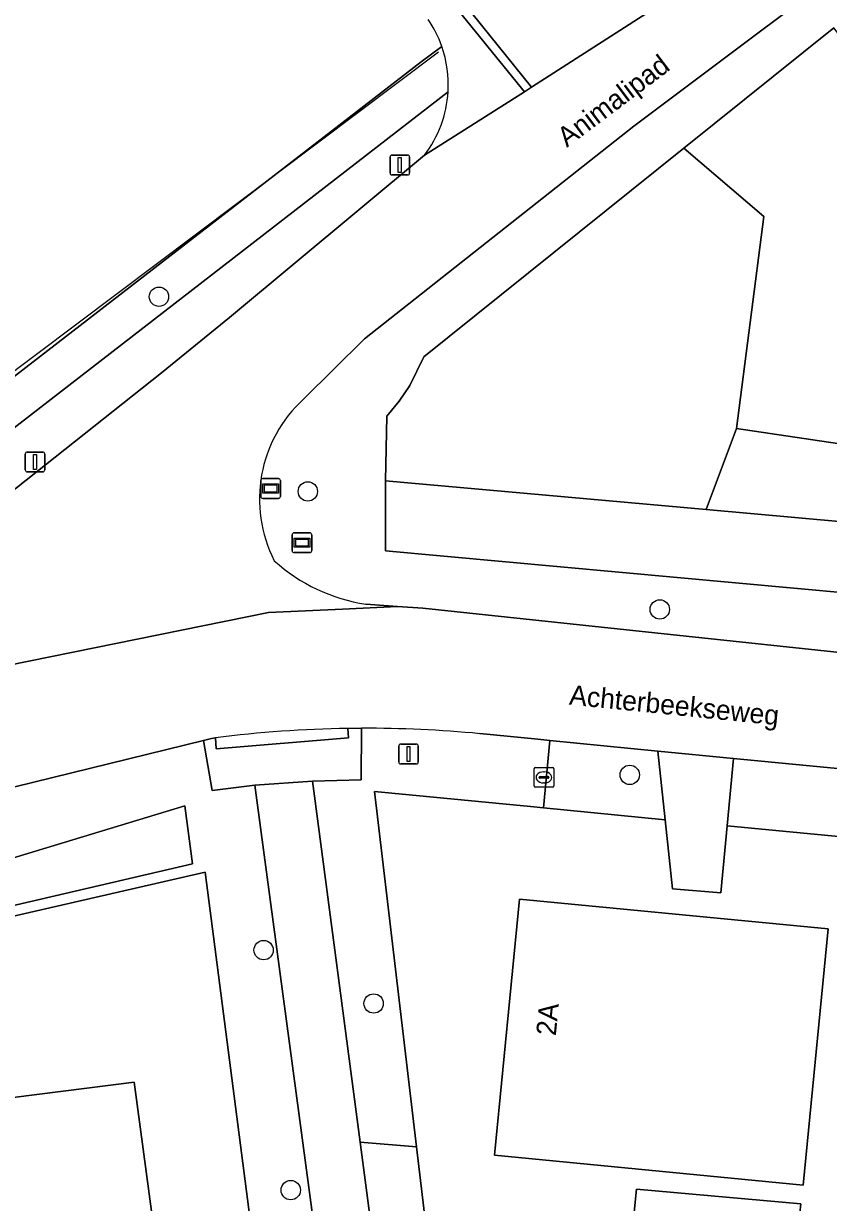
# Model space of a CAD drawing. Extents: x 162156 to 163172, y 378995 to 380779.
# Drawn here: x 162333 to 162373.7, y 380168.4 to 380227.9 of the extents above; entities that cross this region are included whole.
import ezdxf

# ---------------------------------------------------------------- set-up
doc = ezdxf.new("R2010")
doc.units = 0
for name, color, linetype in [('IMGEO_Boom', 7, 'Continuous'), ('IMGEO_Brandkraan', 7, 'Continuous'), ('IMGEO_Erf', 7, 'Continuous'), ('IMGEO_Grasland_overig', 7, 'Continuous'), ('IMGEO_Groenvoorziening', 7, 'Continuous'), ('IMGEO_Hek', 7, 'Continuous'), ('IMGEO_Lichtmast', 7, 'Continuous'), ('IMGEO_Loofbos', 7, 'Continuous'), ('IMGEO_Openbare_ruimte_label', 7, 'Continuous'), ('IMGEO_Pand', 7, 'Continuous'), ('IMGEO_Pand_nummerreeks', 7, 'Continuous'), ('IMGEO_Rijbaan_lokaal_gesloten', 7, 'Continuous'), ('IMGEO_Rijbaan_lokaal_open', 7, 'Continuous'), ('IMGEO_Straatnaambord', 7, 'Continuous'), ('IMGEO_Voetpad_open', 7, 'Continuous'), ('IMGEO_Waterloop', 7, 'Continuous')]:
    doc.layers.add(name, color=color, linetype=linetype)

msp = doc.modelspace()

# ---------------------------------------------------------------- linework, layer by layer
at = {"layer": 'IMGEO_Boom'}
for centre in [(162339.876, 380214.136), (162347.394, 380204.297), (162365.171, 380198.335), (162363.653, 380189.975), (162345.16, 380181.12), (162350.718, 380178.424), (162346.531, 380168.995)]:
    msp.add_circle(centre, 0.489, dxfattribs=at)
at = {"layer": 'IMGEO_Brandkraan'}
for p, q in [((162358.819, 380189.422), (162358.819, 380190.274)), ((162358.894, 380190.348), (162359.746, 380190.348)), ((162359.307, 380190.128), (162359.332, 380190.128)), ((162359.82, 380190.274), (162359.82, 380189.422)), ((162359.078, 380189.842), (162359.078, 380189.854)), ((162359.516, 380189.805), (162359.118, 380189.805)), ((162359.121, 380189.891), (162359.519, 380189.891)), ((162359.33, 380189.568), (162359.305, 380189.568)), ((162359.562, 380189.854), (162359.562, 380189.842)), ((162359.746, 380189.348), (162358.894, 380189.348))]:
    msp.add_line(p, q, dxfattribs=at)
for points in [[(162358.819, 380189.422), (162358.819, 380190.274)], [(162358.894, 380190.348), (162359.746, 380190.348)], [(162359.82, 380190.274), (162359.82, 380189.422)], [(162359.746, 380189.348), (162358.894, 380189.348)]]:
    msp.add_lwpolyline(points, dxfattribs=at)
for centre, radius, start, end in [((162358.896, 380190.272), 0.0765, 91.55205, 178.44795), ((162358.896, 380190.272), 0.0765, 91.55205, 178.44795), ((162359.744, 380190.272), 0.0765, 1.55205, 88.44795), ((162359.744, 380190.272), 0.0765, 1.55205, 88.44795), ((162358.896, 380189.424), 0.0765, 181.55205, 268.44795), ((162358.896, 380189.424), 0.0765, 181.55205, 268.44795), ((162359.118, 380189.851), 0.0403, 85.87752, 175.75265), ((162359.115, 380189.841), 0.0366, 178.93798, 274.71019), ((162359.519, 380189.848), 0.043, 264.86636, 352.45326), ((162359.523, 380189.853), 0.0386, 1.73085, 96.63898), ((162359.744, 380189.424), 0.0765, 271.55205, 358.44795), ((162359.744, 380189.424), 0.0765, 271.55205, 358.44795)]:
    msp.add_arc(centre, radius, start, end, dxfattribs=at)
for centre, major_axis, ratio, start_param, end_param in [((162359.306, 380189.848), (-0.387, 0.002), 0.722429, 4.712389, 7.853982), ((162359.331, 380189.848), (-0.39, 0.002), 0.717154, 1.570796, 4.712389)]:
    msp.add_ellipse(centre, major_axis=major_axis, ratio=ratio, start_param=start_param, end_param=end_param, dxfattribs=at)
at = {"layer": 'IMGEO_Erf'}
for points in [[(162353.115, 380225.997), (162354.159, 380226.783)], [(162307.295, 380189.835), (162306.81, 380192.901), (162310.127, 380192.76), (162353.115, 380225.997)], [(162393.763, 380176.174), (162391.884, 380176.35), (162392.499, 380182.921), (162400.507, 380182.172), (162400.715, 380184.31), (162392.579, 380185.091), (162392.162, 380185.131), (162388.38, 380185.493), (162385.742, 380185.747), (162380.869, 380186.214), (162368.574, 380187.407), (162368.257, 380184.008), (162365.819, 380184.225), (162365.446, 380187.711), (162359.296, 380188.308), (162358.647, 380188.371), (162350.759, 380189.136), (162352.885, 380171.183), (162353.589, 380165.234)]]:
    msp.add_lwpolyline(points, dxfattribs=at)
for points in [[(162372.403, 380169.242), (162356.818, 380170.763), (162358.08, 380183.688), (162373.671, 380182.198)], [(162371.671, 380161.643), (162370.324, 380147.858), (162366.184, 380148.262), (162365.979, 380146.162), (162361.805, 380146.57), (162362.337, 380152.428), (162357.628, 380152.906), (162358.838, 380164.825), (162363.514, 380164.35), (162363.991, 380169.046), (162372.294, 380168.296), (162372.247, 380167.838), (162371.264, 380167.24), (162370.725, 380161.731)]]:
    msp.add_lwpolyline(points, close=True, dxfattribs=at)
msp.add_arc((162348.59, 380224.83), 5.901, 19.32929, 34.20336, dxfattribs=at)
at = {"layer": 'IMGEO_Grasland_overig'}
msp.add_lwpolyline([(162370.419, 380218.19), (162369.037, 380207.472), (162411.795, 380201.127), (162437.143, 380250.174), (162428.501, 380258.734), (162378.58, 380221.695), (162373.96, 380227.724), (162366.385, 380221.643)], close=True, dxfattribs=at)
at = {"layer": 'IMGEO_Groenvoorziening'}
for points in [[(162493.69, 380317.774), (162500, 380321.669), (162508.34, 380326.818), (162512.192, 380329.472), (162511.481, 380331.211), (162505.927, 380327.508), (162484.669, 380313.253), (162476.322, 380307.569), (162468.334, 380301.796), (162450.887, 380288.937), (162395.147, 380246.573), (162372.726, 380229.412), (162372.689, 380229.383), (162370.259, 380227.559), (162363.862, 380222.757), (162350.252, 380212.014), (162347.176, 380208.962)], [(162383.729, 380198.327), (162351.32, 380201.298), (162351.318, 380204.835), (162351.384, 380208.106), (162352.008, 380208.85), (162352.551, 380209.655), (162353.258, 380211.105), (162366.385, 380221.643), (162373.96, 380227.724)], [(162354.159, 380226.783), (162353.115, 380225.997), (162310.127, 380192.76), (162314.733, 380193.715), (162354.477, 380224.489)], [(162354.477, 380224.489), (162314.733, 380193.715), (162318.467, 380194.227)], [(162340.006, 380210.284), (162343.433, 380213.084), (162353.288, 380221.289)], [(162324.772, 380198.212), (162340.006, 380210.284)], [(162350.331, 380198.596), (162351.924, 380198.488), (162353.196, 380198.402), (162382.958, 380195.235)], [(162350.112, 380192.332), (162350.09, 380189.721), (162347.629, 380189.663), (162347.729, 380188.908), (162350.037, 380171.422), (162352.885, 380171.183), (162350.759, 380189.136), (162358.647, 380188.371), (162359.296, 380188.308), (162359.614, 380191.713)], [(162359.614, 380191.713), (162359.007, 380191.772), (162356.076, 380192.058)], [(162408.085, 379703.181), (162408.289, 379704.226), (162408.362, 379710.922), (162407.433, 379718.658), (162402.674, 379750), (162400.562, 379766.602), (162399.53, 379777.438), (162398.595, 379783.512), (162394.073, 379815.929), (162388.914, 379854.445), (162387.247, 379866.948), (162383.975, 379890.989), (162369.543, 380000.044), (162352.327, 380129.869), (162352.7, 380129.905), (162350.587, 380145.671), (162344.822, 380188.69), (162344.718, 380189.464), (162342.565, 380189.181), (162342.118, 380191.718), (162328.735, 380188.436), (162317.977, 380185.472)], [(162289.203, 380186.217), (162277.89, 380189.107), (162278.442, 380184.1), (162278.772, 380184.135), (162278.757, 380184.272), (162292.3, 380181.3), (162302.003, 380178.939), (162304.976, 380178.29), (162308.611, 380177.854), (162309.981, 380177.927), (162316.172, 380179.083), (162342.217, 380185.053), (162346.322, 380153.311), (162346.539, 380151.632), (162347.441, 380145.205), (162349.391, 380131.315), (162352.731, 380105.568), (162366.947, 380000), (162368.464, 379988.666), (162368.623, 379987.477), (162371.684, 379964.606), (162386.534, 379853.639)], [(162306.872, 380178.924), (162302.171, 380179.61), (162297.351, 380180.835), (162290.271, 380182.222), (162278.755, 380184.863), (162279.04, 380186.519), (162289.844, 380183.552), (162297.843, 380182.07), (162302.338, 380181.506), (162309.559, 380180.888), (162312.416, 380181.003), (162315.635, 380181.426), (162319.666, 380182.264), (162327.408, 380184.242), (162341.185, 380188.417), (162341.57, 380185.476), (162316.835, 380179.72)]]:
    msp.add_lwpolyline(points, dxfattribs=at)
for points in [[(162338.626, 380174.447), (162341.504, 380153.008), (162346.322, 380153.311), (162342.217, 380185.053), (162316.172, 380179.083), (162309.981, 380177.927), (162308.611, 380177.854), (162304.976, 380178.29), (162302.003, 380178.939), (162292.3, 380181.3), (162278.757, 380184.272), (162278.772, 380184.135), (162280.517, 380167.715), (162235.526, 380161.77), (162231.086, 380161.186), (162231.132, 380160.825)], [(162347.875, 380105.55), (162341.504, 380153.008), (162338.626, 380174.447), (162231.132, 380160.825), (162234.006, 380138.54), (162234.545, 380138.605), (162235.45, 380138.742), (162239.5, 380111.988), (162238.595, 380111.851), (162237.47, 380111.681), (162239.093, 380099.095), (162240.095, 380091.317)]]:
    msp.add_lwpolyline(points, close=True, dxfattribs=at)
for centre, radius, start, end in [((162348.633, 380224.848), 5.855, 356.48556, 19.29881), ((162348.628, 380224.841), 5.859, 322.6802, 356.55344), ((162351.81, 380203.904), 6.86, 132.4924, 206.95101), ((162351.674, 380207.414), 8.919, 227.90716, 261.33994), ((162350.371, 380132.934), 59.398, 84.48886, 90.25024)]:
    msp.add_arc(centre, radius, start, end, dxfattribs=at)
at = {"layer": 'IMGEO_Hek'}
for points in [[(162325.53, 380205.107), (162353.989, 380226.515)], [(162342.217, 380185.053), (162316.172, 380179.083), (162309.981, 380177.927), (162308.611, 380177.854), (162304.976, 380178.29), (162302.003, 380178.939), (162292.3, 380181.3)], [(162346.322, 380153.311), (162342.217, 380185.053)]]:
    msp.add_lwpolyline(points, dxfattribs=at)
at = {"layer": 'IMGEO_Lichtmast'}
for p, q in [((162351.544, 380220.389), (162351.544, 380221.189)), ((162351.544, 380221.189), (162351.544, 380220.389)), ((162351.644, 380221.289), (162352.434, 380221.289)), ((162352.434, 380221.289), (162351.644, 380221.289)), ((162352.534, 380221.189), (162352.534, 380220.389)), ((162352.534, 380220.389), (162352.534, 380221.189)), ((162352.434, 380220.289), (162351.644, 380220.289)), ((162351.644, 380220.289), (162352.434, 380220.289)), ((162333.119, 380205.386), (162333.119, 380206.186)), ((162333.119, 380206.186), (162333.119, 380205.386)), ((162333.219, 380206.286), (162334.009, 380206.286)), ((162334.009, 380206.286), (162333.219, 380206.286)), ((162334.109, 380206.186), (162334.109, 380205.386)), ((162334.109, 380205.386), (162334.109, 380206.186)), ((162334.009, 380205.286), (162333.219, 380205.286)), ((162333.219, 380205.286), (162334.009, 380205.286)), ((162351.983, 380190.629), (162351.983, 380191.429)), ((162351.983, 380191.429), (162351.983, 380190.629)), ((162352.083, 380191.529), (162352.873, 380191.529)), ((162352.873, 380191.529), (162352.083, 380191.529)), ((162352.973, 380191.429), (162352.973, 380190.629)), ((162352.973, 380190.629), (162352.973, 380191.429)), ((162352.873, 380190.529), (162352.083, 380190.529)), ((162352.083, 380190.529), (162352.873, 380190.529))]:
    msp.add_line(p, q, dxfattribs=at)
for points in [[(162351.964, 380221.164), (162352.114, 380221.164), (162352.114, 380220.414), (162351.964, 380220.414), (162351.964, 380221.164)], [(162333.539, 380206.161), (162333.689, 380206.161), (162333.689, 380205.411), (162333.539, 380205.411), (162333.539, 380206.161)], [(162352.403, 380191.404), (162352.553, 380191.404), (162352.553, 380190.654), (162352.403, 380190.654), (162352.403, 380191.404)]]:
    msp.add_lwpolyline(points, dxfattribs=at)
for centre, start, end in [((162351.644, 380221.189), 90, 180), ((162351.644, 380221.189), 90, 180), ((162352.434, 380221.189), 0, 90), ((162352.434, 380221.189), 360, 90), ((162351.644, 380220.389), 180, 270), ((162351.644, 380220.389), 180, 270), ((162352.434, 380220.389), 270, 0), ((162352.434, 380220.389), 270, 0), ((162333.219, 380206.186), 90, 180), ((162333.219, 380206.186), 90, 180), ((162334.009, 380206.186), 0, 90), ((162334.009, 380206.186), 360, 90), ((162333.219, 380205.386), 180, 270), ((162333.219, 380205.386), 180, 270), ((162334.009, 380205.386), 270, 0), ((162334.009, 380205.386), 270, 0), ((162352.083, 380191.429), 90, 180), ((162352.083, 380191.429), 90, 180), ((162352.873, 380191.429), 0, 90), ((162352.873, 380191.429), 360, 90), ((162352.083, 380190.629), 180, 270), ((162352.083, 380190.629), 180, 270), ((162352.873, 380190.629), 270, 0), ((162352.873, 380190.629), 270, 0)]:
    msp.add_arc(centre, 0.1, start, end, dxfattribs=at)
at = {"layer": 'IMGEO_Loofbos'}
msp.add_lwpolyline([(162367.515, 380203.379), (162369.037, 380207.472), (162370.419, 380218.19), (162366.385, 380221.643), (162353.258, 380211.105), (162352.551, 380209.655), (162352.008, 380208.85), (162351.384, 380208.106), (162351.318, 380204.835)], close=True, dxfattribs=at)
msp.add_lwpolyline([(162411.795, 380201.127), (162369.037, 380207.472), (162367.515, 380203.379), (162388.412, 380201.5)], dxfattribs=at)
at = {"layer": 'IMGEO_Pand'}
for points in [[(162373.671, 380182.198), (162358.08, 380183.688), (162356.818, 380170.763), (162372.403, 380169.242)], [(162371.671, 380161.643), (162370.725, 380161.731), (162371.264, 380167.24), (162372.247, 380167.838), (162372.294, 380168.296), (162363.991, 380169.046), (162363.514, 380164.35), (162358.838, 380164.825), (162357.628, 380152.906), (162362.337, 380152.428), (162361.805, 380146.57), (162365.979, 380146.162), (162366.184, 380148.262), (162370.324, 380147.858)]]:
    msp.add_lwpolyline(points, close=True, dxfattribs=at)
at = {"layer": 'IMGEO_Rijbaan_lokaal_gesloten'}
for points in [[(162347.176, 380208.962), (162350.252, 380212.014), (162363.862, 380222.757), (162370.259, 380227.559), (162372.689, 380229.383), (162372.726, 380229.412), (162395.147, 380246.573), (162450.887, 380288.937), (162468.334, 380301.796), (162476.322, 380307.569), (162484.669, 380313.253), (162505.927, 380327.508), (162511.481, 380331.211), (162514.906, 380333.495), (162527.032, 380341.73)], [(162381.999, 380241.493), (162372.733, 380234.326), (162366.037, 380229.487), (162365.645, 380229.204), (162358.695, 380224.728), (162358.331, 380224.494), (162353.288, 380221.289), (162343.433, 380213.084), (162340.006, 380210.284), (162324.772, 380198.212)], [(162310.176, 380190.435), (162329.976, 380195.039), (162345.414, 380198.175), (162349.145, 380198.355), (162351.924, 380198.488), (162350.331, 380198.596)], [(162419.663, 380191.175), (162393.262, 380193.962), (162392.976, 380193.997), (162382.958, 380195.235), (162353.196, 380198.402), (162351.924, 380198.488), (162349.145, 380198.355), (162345.414, 380198.175), (162329.976, 380195.039), (162310.176, 380190.435)], [(162317.977, 380185.472), (162328.735, 380188.436), (162342.118, 380191.718), (162342.53, 380191.819), (162342.628, 380191.832), (162342.726, 380191.844)], [(162349.415, 380192.326), (162350.112, 380192.332)], [(162356.076, 380192.058), (162359.007, 380191.772), (162359.614, 380191.713), (162365.074, 380191.181), (162368.891, 380190.809), (162379.916, 380189.734), (162381.418, 380189.588), (162386.064, 380189.196), (162388.705, 380188.974), (162392.932, 380188.444), (162394.165, 380188.29), (162401.096, 380187.421), (162438.155, 380182.942), (162449.679, 380181.534), (162500.017, 380174.692), (162550.923, 380167.352), (162568.43, 380164.415), (162568.532, 380164.853), (162570.527, 380164.538)]]:
    msp.add_lwpolyline(points, dxfattribs=at)
for centre, radius, start, end in [((162351.81, 380203.904), 6.86, 132.4924, 206.95101), ((162351.674, 380207.414), 8.919, 227.90716, 261.33994), ((162350.355, 380132.621), 59.712, 90.90236, 97.3407), ((162350.371, 380132.934), 59.398, 84.48886, 90.25024)]:
    msp.add_arc(centre, radius, start, end, dxfattribs=at)
at = {"layer": 'IMGEO_Rijbaan_lokaal_open'}
for points in [[(162350.638, 380233.965), (162358.331, 380224.494), (162358.695, 380224.728), (162353.988, 380230.568), (162350.941, 380234.293)], [(162350.941, 380234.293), (162353.988, 380230.568), (162358.695, 380224.728), (162365.645, 380229.204), (162366.037, 380229.487)]]:
    msp.add_lwpolyline(points, dxfattribs=at)
msp.add_lwpolyline([(162350.037, 380171.422), (162347.729, 380188.908), (162347.629, 380189.663), (162344.718, 380189.464), (162344.822, 380188.69), (162350.587, 380145.671), (162353.39, 380146.024), (162352.596, 380152.04), (162352.394, 380153.567), (162351.553, 380159.939), (162351.338, 380161.569), (162350.816, 380165.525)], close=True, dxfattribs=at)
at = {"layer": 'IMGEO_Straatnaambord'}
for p, q in [((162345.118, 380204.947), (162345.908, 380204.947)), ((162345.908, 380204.947), (162345.118, 380204.947)), ((162345.018, 380204.047), (162345.018, 380204.847)), ((162345.018, 380204.847), (162345.018, 380204.047)), ((162346.008, 380204.847), (162346.008, 380204.047)), ((162346.008, 380204.047), (162346.008, 380204.847)), ((162345.908, 380203.947), (162345.118, 380203.947)), ((162345.118, 380203.947), (162345.908, 380203.947)), ((162346.601, 380201.307), (162346.601, 380202.107)), ((162346.601, 380202.107), (162346.601, 380201.307)), ((162346.701, 380202.207), (162347.491, 380202.207)), ((162347.491, 380202.207), (162346.701, 380202.207)), ((162347.591, 380202.107), (162347.591, 380201.307)), ((162347.591, 380201.307), (162347.591, 380202.107)), ((162347.491, 380201.207), (162346.701, 380201.207)), ((162346.701, 380201.207), (162347.491, 380201.207))]:
    msp.add_line(p, q, dxfattribs=at)
for points in [[(162345.119, 380204.679), (162345.907, 380204.679), (162345.907, 380204.215), (162345.119, 380204.215), (162345.119, 380204.679)], [(162345.184, 380204.614), (162345.184, 380204.28), (162345.842, 380204.28), (162345.842, 380204.614), (162345.184, 380204.614)], [(162346.702, 380201.939), (162347.49, 380201.939), (162347.49, 380201.475), (162346.702, 380201.475), (162346.702, 380201.939)], [(162346.767, 380201.874), (162346.767, 380201.54), (162347.425, 380201.54), (162347.425, 380201.874), (162346.767, 380201.874)]]:
    msp.add_lwpolyline(points, dxfattribs=at)
for centre, start, end in [((162345.118, 380204.847), 90, 180), ((162345.118, 380204.847), 90, 180), ((162345.908, 380204.847), 0, 90), ((162345.908, 380204.847), 360, 90), ((162345.118, 380204.047), 180, 270), ((162345.118, 380204.047), 180, 270), ((162345.908, 380204.047), 270, 0), ((162345.908, 380204.047), 270, 0), ((162346.701, 380202.107), 90, 180), ((162346.701, 380202.107), 90, 180), ((162347.491, 380202.107), 0, 90), ((162347.491, 380202.107), 360, 90), ((162346.701, 380201.307), 180, 270), ((162346.701, 380201.307), 180, 270), ((162347.491, 380201.307), 270, 0), ((162347.491, 380201.307), 270, 0)]:
    msp.add_arc(centre, 0.1, start, end, dxfattribs=at)
at = {"layer": 'IMGEO_Voetpad_open'}
for points in [[(162353.288, 380221.289), (162358.331, 380224.494), (162350.638, 380233.965)], [(162342.726, 380191.844), (162342.772, 380191.29), (162349.455, 380191.84), (162349.415, 380192.326)]]:
    msp.add_lwpolyline(points, dxfattribs=at)
for points in [[(162350.112, 380192.332), (162349.415, 380192.326), (162349.455, 380191.84), (162342.772, 380191.29), (162342.726, 380191.844), (162342.628, 380191.832), (162342.53, 380191.819), (162342.118, 380191.718), (162342.565, 380189.181), (162344.718, 380189.464), (162347.629, 380189.663), (162350.09, 380189.721)], [(162365.074, 380191.181), (162359.614, 380191.713), (162359.296, 380188.308), (162365.446, 380187.711)], [(162368.891, 380190.809), (162365.074, 380191.181), (162365.446, 380187.711), (162365.819, 380184.225), (162368.257, 380184.008), (162368.574, 380187.407)], [(162379.916, 380189.734), (162368.891, 380190.809), (162368.574, 380187.407), (162380.869, 380186.214)], [(162352.885, 380171.183), (162350.037, 380171.422), (162350.816, 380165.525), (162353.589, 380165.234)]]:
    msp.add_lwpolyline(points, close=True, dxfattribs=at)
for centre, radius, start, end in [((162348.59, 380224.83), 5.901, 19.32929, 34.20336), ((162348.633, 380224.848), 5.855, 356.48556, 19.29881), ((162348.628, 380224.841), 5.859, 322.6802, 356.55344), ((162350.355, 380132.621), 59.712, 90.90236, 97.3407)]:
    msp.add_arc(centre, radius, start, end, dxfattribs=at)
at = {"layer": 'IMGEO_Waterloop'}
msp.add_lwpolyline([(162388.412, 380201.5), (162367.515, 380203.379), (162351.318, 380204.835), (162351.32, 380201.298), (162383.729, 380198.327), (162400.16, 380196.679), (162400.445, 380199.626)], close=True, dxfattribs=at)
msp.add_lwpolyline([(162316.835, 380179.72), (162341.57, 380185.476), (162341.185, 380188.417), (162327.408, 380184.242), (162319.666, 380182.264), (162315.635, 380181.426), (162312.416, 380181.003), (162309.559, 380180.888), (162302.338, 380181.506), (162297.843, 380182.07), (162289.844, 380183.552), (162279.04, 380186.519), (162278.755, 380184.863), (162290.271, 380182.222), (162297.351, 380180.835), (162302.171, 380179.61), (162306.872, 380178.924)], dxfattribs=at)

# ---------------------------------------------------------------- texts
at = {"layer": 'IMGEO_Openbare_ruimte_label'}
for s, rotation, p in [('Animalipad', 37.03039, (162360.476, 380221.654)), ('Achterbeekseweg', 354.31792, (162360.565, 380193.529))]:
    msp.add_text(s, height=1, rotation=rotation, dxfattribs=at).set_placement(p)
at = {"layer": 'IMGEO_Pand_nummerreeks'}
msp.add_text('2A', height=1, rotation=84.42533, dxfattribs=at).set_placement((162359.917, 380176.768))

doc.saveas('drawing.dxf')
